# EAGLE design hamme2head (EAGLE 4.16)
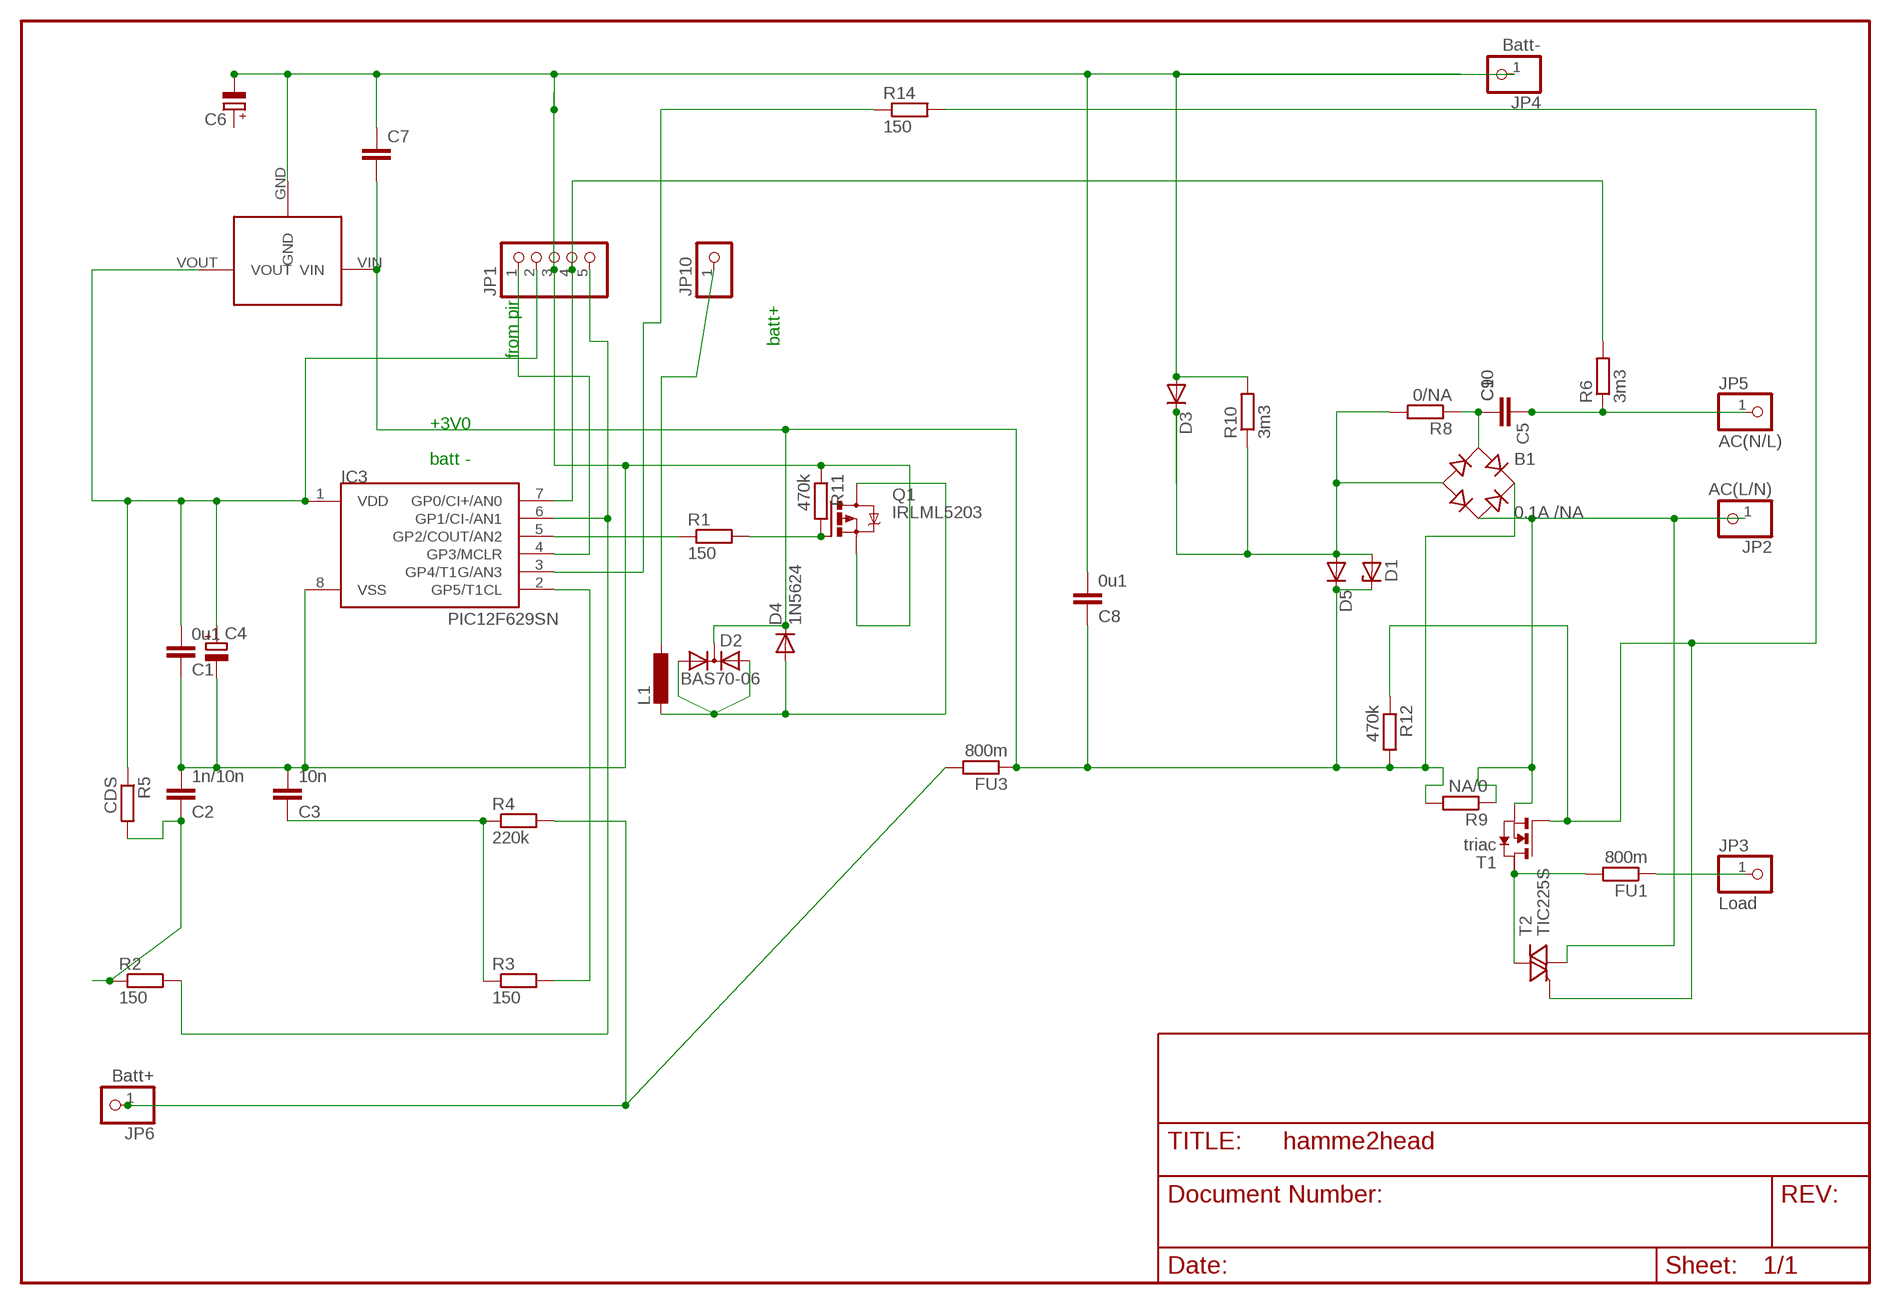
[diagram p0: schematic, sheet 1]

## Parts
B1  0.1A /NA  RECTIFIER-B40S  [B40S]
C1  0u1  C-EUC1206  [C1206]
C2  1n/10n  C-EUC1206  [C1206]
C3  10n  C-EUC1206  [C1206]
C4  CPOL-EUE2.5-6  [E2,5-6]
C5  C-EU050-025X075  [C050-025X075]
C6  CPOL-EUE2,5-6E  [E2,5-6E]
C7  C-EUC0805  [C0805]
C8  0u1  C-EUC1206  [C1206]
C9  C-EU075-032X103  [C075-032X103]
C10  C-EU102-043X133  [C102-043X133]
D1  ZENER-DIODESOT23  [SOT23]
D2  BAS70-06  [SOT23]
D3  DIODE-MELF-MLL41  [MELF-MLL41]
D4  1N5624  [DO201-15]
D5  DIODE-MINIMELF  [MINIMELF]
FU1  800m  R-EU_0204/5  [0204/5]
FU3  800m  R-EU_0204/7  [0204/7]
IC3  PIC12F629SN  [SO-08]
JP1  PINHD-1X5  [1X05]
JP2  AC(L/N)  PINHD-1X1  [1X01]
JP3  Load  PINHD-1X1  [1X01]
JP4  Batt-  PINHD-1X1  [1X01]
JP5  AC(N/L)  PINHD-1X1  [1X01]
JP6  Batt+  PINHD-1X1  [1X01]
JP10  PINHD-1X1  [1X01]
L1  L-EU2200-15.24  [2200-15.24]
Q1  IRLML5203  [MICRO3]
R1  150  R-EU_0207/15  [0207/15]
R2  150  R-EU_R0805  [R0805]
R3  150  R-EU_R0805  [R0805]
R4  220k  R-EU_R0805  [R0805]
R5  CDS  R-EU_0411/3V  [0411V]
R6  3m3  R-EU_R1206  [R1206]
R8  0/NA  R-EU_R0402  [R0402]
R9  NA/0  R-EU_R0402  [R0402]
R10  3m3  R-EU_R1206  [R1206]
R11  470k  R-EU_R0805  [R0805]
R12  470k  R-EU_R0805  [R0805]
R14  150  R-EU_0617/22  [0617/22]
T1  triac  NMOSSOT223  [SOT223]
T2  TIC225S  [TO220DS]
U$1  VREG-S  [TO92-S]

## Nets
GND: C1.1 C2.2 C3.2 C4.- C6.- C7.1 C8.2 D3.A IC3.8(VSS) JP1.3 JP4.1 Q1.2(S) R10.2 R11.1 U$1.GND
N$2: IC3.6(GP1/CI-/AN1) JP1.5 R2.2
N$4: R12.1 R14.2 T1.1(G) T2.G
N$5: D2.1(A1) D2.2(A2) D4.A L1.2 Q1.3(D)
N$7: C3.1 R3.1 R4.1
N$8: IC3.2(GP5/T1CL) R3.2
N$9: IC3.4(GP3/MCLR) JP1.1
N$11: C2.1 R2.1 R5.2
N$12: IC3.5(GP2/COUT/AN2) R1.1
N$14: IC3.7(GP0/CI+/AN0) JP1.4 R6.2
N$17: JP10.1 L1.1
N$18: FU1.1 JP3.1
N$19: FU1.2 T1.2(D) T2.A2
N$20: Q1.1(G) R1.2 R11.2
N$21: IC3.3(GP4/T1G/AN3) R14.1
N$23: B1.AC2 JP2.1 R9.1 T1.3(S) T2.A1
N$25: B1.- D1.1(A) D3.C D5.A R8.2 R10.1
N$26: B1.AC1 C5.2 C9.1 C10.1 R8.1
N$36: FU3.2 JP6.1 R4.2
N$37: C5.1 C9.2 C10.2 JP5.1 R6.1
RECT+: B1.+ C7.2 C8.1 D1.3(C) D2.3(C) D4.C D5.C FU3.1 R9.2 R12.2 U$1.VIN
VOUT+: C1.2 C4.+ IC3.1(VDD) JP1.2 R5.1 U$1.VOUT
Unconnected: C6.+ T1.4(D2)

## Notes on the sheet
- batt+
- from pir
- +3V0
- batt -

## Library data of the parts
B1 = rectifier:RECTIFIER-: Rectifier
C1-C3 C5 C8-C10 = rcl:C-EU: CAPACITOR, European symbol
C4 C6 = rcl(2):CPOL-EU: POLARIZED CAPACITOR, European symbol
C7 = rcl(2):C-EU: CAPACITOR, European symbol
D1 = diode-1:ZENER-DIODE: Z-Diode
D2 = diode-1:BAS70-06: Silicon Schottky Diodes General-purpose diode for high-speed switching
D3 D5 = diode-1:DIODE-: DIODE
D4 = diode:1N5624: DIODE
FU1 FU3 R1-R6 R8-R12 R14 = rcl:R-EU_: RESISTOR, European symbol
IC3 = microchip-3:PIC12F6*: uPC nW 1k Program Flash memory 2x Timer Comparator 10b A/D converter/ 4xIN
JP1 = pinhead(2):PINHD-1X5: PIN HEADER
JP2-JP6 = pinhead:PINHD-1X1: PIN HEADER
JP10 = pinhead(2):PINHD-1X1: PIN HEADER
L1 = rcl:L-EU: INDUCTOR, European symbol
Q1 = transistor-power:IRLML5203: HEXFET P-Channel Power MOSFET
T1 = zetex:NMOSSOT223: MOS FET
T2 = triac:TIC225S: TRIAC
U$1 = spoton:VREG-S: vreg aus spoton

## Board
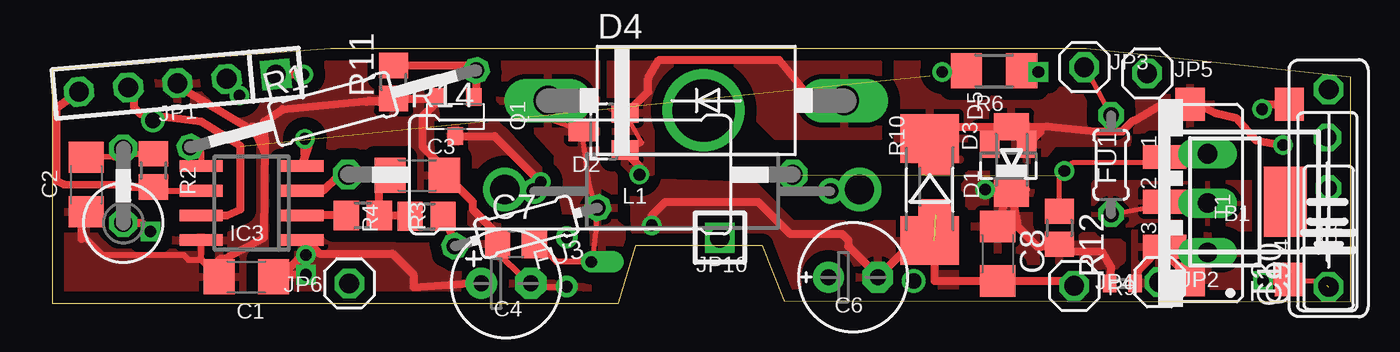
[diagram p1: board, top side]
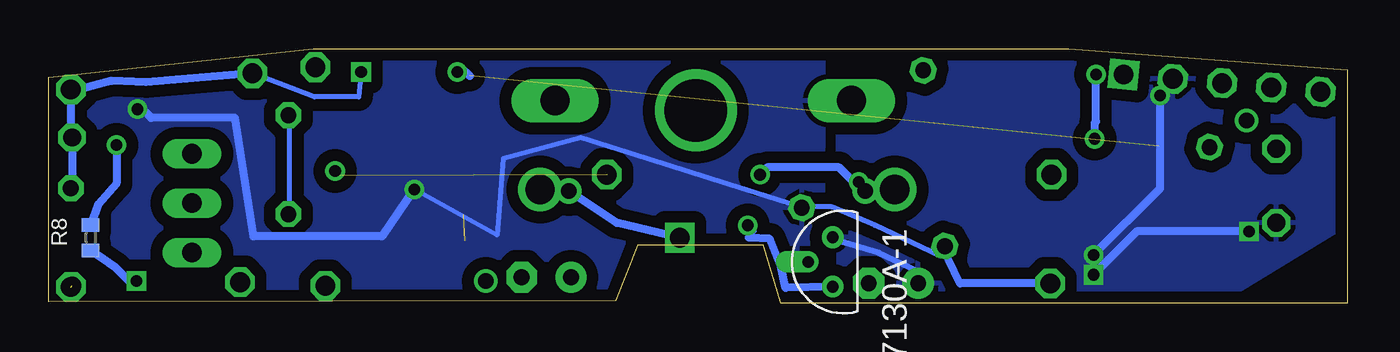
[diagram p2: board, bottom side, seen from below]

Size 66.76 x 13.08 mm. Coordinates in mm from the lower left corner, seen from the top.
Outline: 0,0 29.11,0 30,2.98 36.47,2.98 37.62,0.12 66.76,0.06 66.76,11.61 53.18,13.07 52.41,13.08 18,13.07 14.31,13.08 0,11.99 0,0
Copper layers (1*16): Top 0.035mm / dielectric 1.5mm / Bottom 0.035mm
Design rules "default": minimum track width 10mil, minimum drill 2mil, track to track 8mil, track to pad 8mil, pad to pad 8mil, via to via 8mil, smd to smd 8mil, copper to edge 1mil, drill to drill 8mil, minimum pad ring 10mil, minimum via ring 8mil, stop-mask expansion 4mil, vias tented up to drill 0mil, thermal gap 10mil

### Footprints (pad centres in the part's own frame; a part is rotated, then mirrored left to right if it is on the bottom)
B40S = smd 1.5 x 1.7: + -2.55,-4.5; - 2.55,-4.5; AC1 -2.55,4.5; AC2 2.55,4.5
C1206 = smd 1.6 x 1.8: 1 -1.4,0; 2 1.4,0
E2,5-6 = drill 0.813 pad 1.6 round: + -1.27,0 | drill 0.813 pad 1.6 octagon: - 1.27,0
C050-025X075 = drill 0.813 octagon: 1 -2.54,0; 2 2.54,0
E2,5-6E = drill 0.813 pad 1.575 round: + -1.27,0 | drill 0.813 pad 1.575 octagon: - 1.27,0
C0805 = smd 1.3 x 1.5: 1 -0.95,0; 2 0.95,0
C075-032X103 = drill 0.914 octagon: 1 -3.81,0; 2 3.81,0
C102-043X133 = drill 1.016 octagon: 1 -5.08,0; 2 5.08,0
SOT23 = smd 1 x 1.4: 1 -0.95,-1.1; 2 0.95,-1.1; 3 0,1.1
MELF-MLL41 = smd 2.5 x 3: A 2.625,0; C -2.625,0
DO201-15 = drill 1.499 long: A 7.62,0; C -7.62,0
MINIMELF = smd 1.4 x 1.8: A 1.7,0; C -1.7,0
0204/5 = drill 0.813 octagon: 1 -2.54,0; 2 2.54,0
0204/7 = drill 0.813 octagon: 1 -3.81,0; 2 3.81,0
SO-08 = smd 0.6 x 2.2: 1 -1.905,-2.6; 2 -0.635,-2.6; 3 0.635,-2.6; 4 1.905,-2.6; 5 1.905,2.6; 6 0.635,2.6; 7 -0.635,2.6; 8 -1.905,2.6
1X05 = drill 1.016 square: 1 -5.08,0 | drill 1.016 octagon: 2 -2.54,0; 3 0,0; 4 2.54,0; 5 5.08,0
1X01 = drill 1.016 octagon: 1 0,0
1X01' = drill 1.016 square: 1 0,0
2200-15.24 = drill 0.8 pad 1.27 round: 1 -7.62,0; 2 7.62,0
MICRO3 = smd 0.8 x 0.9: 1 -0.95,-1; 2 0.95,-1; 3 0,1
0207/15 = drill 0.813 octagon: 1 -7.62,0; 2 7.62,0
R0805 = smd 1.3 x 1.5: 1 -0.85,0; 2 0.85,0
0411V = drill 0.914 octagon: 1 -2.54,0; 2 1.27,0
R1206 = smd 1.6 x 1.803: 1 -1.422,0; 2 1.422,0
R0402 = smd 0.7 x 0.9: 1 -0.65,0; 2 0.65,0
0617/22 = drill 1.016 octagon: 1 -11.43,0; 2 11.43,0
SOT223 = smd 1.219 x 2.235: 1 -2.311,-3.099; 2 0,-3.099; 3 2.311,-3.099 | smd 3.6 x 2.2: 4 0,3.099
TO220DS = drill 1.016 long: A1 -2.54,-2.54; A2 0,-2.54; G 2.54,-2.54
TO92-S = drill 0.6 round: GND -2.54,0; VOUT 0,0 | drill 0.6 offset: VIN -1.27,1.27

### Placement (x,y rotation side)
B1  61.05,5.71 180 top
C1  9.98,1.34 0 top
C2  1.74,6.09 270 top
C3  18.76,6.56 0 top
C4  23.33,1.01 0 top
C5  65.62,3.36 270 top
C6  41.17,1.33 0 top
C7  23.84,3.04 0 top
C8  48.6,2.54 270 top
C9  65.56,4.69 90 top
C10  65.62,5.9 90 top
D1  49.15,7.06 180 top
D2  28.35,8.82 90 top
D3  45.11,5.84 270 top
D4  33.11,10.41 0 top
D5  49.32,7.36 90 top
FU1  54.43,7.11 270 top
FU3  24.36,3.91 195 top
IC3  10.25,5.14 90 top
JP1  6.43,11.3 185 top
JP2  56.92,1.07 0 top
JP3  53.05,12.12 0 top
JP4  52.54,0.88 0 top
JP5  56.29,11.81 0 top
JP6  15.27,1.01 0 top
JP10  [1X01']  34.32,3.36 0 top
L1  32.4,5.75 180 top
Q1  20.73,9.58 180 top
R1  14.44,9.99 15 top
R2  5.19,6.82 270 top
R3  15.96,4.5 180 top
R4  19.24,4.47 0 top
R5  3.65,6.66 90 top
R6  48.41,11.93 180 top
R8  64.6,3.36 90 bottom
R9  55.02,1.01 180 top
R10  45.43,5.96 270 top
R11  17.55,11.36 90 top
R12  51.78,3.87 270 top
R14  26.63,6.6 0 top
T1  60.29,5.2 270 top
T2  56.86,5.14 90 top
U$1  26.45,3.38 90 bottom

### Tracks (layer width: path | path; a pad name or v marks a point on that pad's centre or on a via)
GND  (via drill 0.6)  (1 unrouted)
  Top 0.305: C1.1 8.55,1.34 8.53,1.33 8.12,1.74 7.68,2.19 | IC3.8 7.65,2.21 7.68,2.19 | C7.1 22.63,2.85 24.47,1.01 C4.- 24.77,0.84 U$1.GND | 7.68,2.19 7.71,2.22 7.01,2.22 6.76,2.47 2.57,2.47 1.74,3.3 1.49,3.3 | 7.68,2.19 | C2.2 1.48,4.75 1.3,4.57
  Top 0.406: 10.95,8.31 10.88,3.36 8.85,2.28 8.66,2.28 8.12,1.74 | 8.12,1.74 8.09,1.71 | 8.12,1.74 | C7.1 22.89,3.17 22.95,3.23 22.82,3.36 22.82,3.61 21.62,4.82 21.62,5.2 20.6,6.22 20.54,6.22 20.16,6.6 | JP4.1 52.41,0.88 52.41,1.14 C8.2 45.36,1.14 45.36,3.21 D3.A 44.33,3.21 C6.- 42.44,1.39 40.92,2.92 40.92,3.23 40.6,3.55 37.94,3.55 36.28,5.2 31.52,5.2 30.82,4.5 v30.82,4 | 20.16,6.6 | 20.16,6.6 C3.2 20.16,6.91 19.01,8.06 19.01,9.58 19.78,10.35 Q1.2 19.78,10.54 19.65,10.41 19.54,10.51 R11.1 17.55,10.41 17.49,10.35 16.79,10.35 | 16.79,10.35 16.15,10.35 | C2.2 1.86,4.69 1.49,4.31 1.49,3.3 | JP1.3 6.43,11.24 6.7,10.97 6.75,10.97 10.12,8.95 10.31,9.08 10.88,7.81 10.95,8.31 | 10.95,8.31 10.88,9.33 11.84,9.96 16.28,10.41 16.79,10.41 16.79,10.35
  Bottom 0.406: U$1.GND 28.88,0.78 29.11,1.9 29.68,3.3 30.76,3.36 30.57,3.74 v30.82,4
  pour Top (isolate 0.61, rank 3): 29.87,5.39 29.93,3.74 30,3.55 36.03,3.55 36.98,2.6 36.98,1.84 38.32,0.5 46.32,0.5 46.44,0.63 46.44,1.65 44.03,4.06 38.06,4.06 36.09,6.03 30.44,6.22 30.06,5.84 30,5.65
  pour Top (isolate 0.61, rank 3): 0.15,11.49 0.15,1.27 0.85,0.57 27.71,0.57 25.3,3.93 20.85,4.69 19.08,12.69 1.74,12.57 0.66,11.49
N$2
  Top 0.305: R2.2 5.19,5.88 5.3,5.77 IC3.6
  Top 0.406: R2.2 3.51,5.97 3.39,6.09 0.59,6.1 0.22,6.28 0.22,10.03 JP1.5 | JP1.5 1.49,10.98 | JP1.5
N$3
  Bottom 0.254: 20.92,2.41 24.28,4 26.51,4.95 27.97,4.95
N$4  (1 unrouted)
  Top 0.254: R12.1 51.78,6.54 52.48,7.23 56.29,7.23 56.48,7.42 56.98,7.42 | T2.G 59.33,7.74 59.02,7.42 56.98,7.42 | 56.98,7.42 56.98,7.55 57.02,7.51 T1.1
N$5  (via drill 0.6)
  Top 0.254: D2.1 30.32,8.25 D2.2 | L1.2 24.85,6.03
  Top 0.406: Q1.3 22.74,8.58 v25.11,6.22 25.11,6.03 24.83,5.75 L1.2 | D4.A 39.08,10.41 37.36,12.5 31.2,12.5 30.63,11.55 30.63,10.85 29.55,9.77 D2.2 | D2.1 29.45,7.83 29.43,7.81 30.19,7.04 v30.19,6.6
  Bottom 0.406: v25.11,6.22 25.36,6.22 26.12,6.98 29.81,6.98 v30.19,6.6
  pour Top (isolate 0.61, rank 3): 28.73,10.03 28.73,12.69 28.79,12.76 42,12.76 42.7,12.06 42.7,8.76 42.51,8.57 37.24,8.57 35.46,10.35 31.78,10.35 30.76,9.33 30.76,6.79 30.82,6.73 29.87,6.73 28.98,7.62 28.98,9.9 28.85,10.03
  pour Top (isolate 0.61, rank 2): 20.41,9.01 22.95,9.14 25.49,6.34 23.96,4.82 23.2,4.82 20.73,7.3
N$7
  Top 0.406: C3.1 17.36,6.48 17.36,6.47 16.81,5.92 R3.1 18.25,4.5 18.31,4.44 18.34,4.47 R4.1
N$8
  Top 0.406: R3.2 15.08,4.5 15.01,4.44 14.95,4.5 IC3.2
N$9  (via drill 0.6)
  Top 0.406: IC3.4 12.85,7.1 13.17,8.06 13.17,8.19 12.98,7.62 v12.98,8.44 | JP1.1 v12.91,11.75 v12.92,11.74
  Bottom 0.406: v12.98,8.44 12.98,9.27 12.92,9.33 v12.92,11.74
N$11
  Top 0.305: 3.91,7.67 4.03,7.67 R2.1 | C2.1 3.14,7.55
  Top 0.406: 3.14,7.55 3.39,7.55 3.64,7.81 R5.2 3.71,7.93 4.03,7.62 4.03,7.67
N$12
  Top 0.305: R1.1 7.49,8.22 7.58,8.25 7.65,7.68 IC3.5
N$14  (via drill 0.6)  (1 unrouted)
  Top 0.406: IC3.7 8.98,4.5 9.68,4.82 9.68,8.06 7.65,9.33 4.53,9.71 4.22,10.03 4.22,10.92 4.05,11.08 JP1.4 | R6.2 45.81,11.93 v45.75,11.87
  Bottom 0.406: v45.75,11.87 45.3,11.87 45.11,11.68
N$15  (via drill 1.5)
  other vias: 41.49,5.84
N$16  (via drill 1.5)
  other vias: 23.27,5.84
N$17
  Bottom 0.406: L1.1 37.55,4.12 JP10.1
N$18
  Top 0.254: JP3.1 53.11,12.12 FU1.1
N$19
  Top 0.254: 57.23,5.08 57.19,5.13 T1.2 59.27,5.2 59.4,5.08 T2.A2 | FU1.2 57.23,5.08 | 57.23,5.08 57.24,5.08
  pour Top (isolate 0.61): 53.62,6.22 62.26,6.22 62.51,5.96 62.51,3.87 62.57,3.81 60.92,3.81 60.73,4 53.68,4 53.56,4.19 53.56,6.15
N$20
  Top 0.406: R11.2 21.85,12.21 21.93,12.12 21.8,11.99 R1.2 21.8,10.8 21.81,10.79 21.68,10.66 Q1.1
N$21
  Top 0.406: IC3.3 13.93,5.77 14.63,6.47 15.08,6.47 R14.1
N$23
  Top 0.406: T2.A1 59.4,2.47 58.5,1.57 B1.AC2 58.5,1.28 57.19,2.59 T1.3 57,2.87 55.86,1.73 R9.1
  pour Top (isolate 0.61): 55.65,0.44 60.99,0.5 60.99,3.36 55.65,3.61
N$24  (via drill 0.6)
  other vias: 52.03,6.79
N$25  (via drill 0.6)
  Top 0.406: 50.81,9.06 51.14,9.08 53.62,8.82 55.02,8.82 55.59,9.39 55.65,9.39 57.04,10.21 B1.- 58.75,10.21 58.83,10.28 59.78,9.77 60.86,9.52 61.87,8.38 v63.27,8.12 | 50.81,9.06 D5.A 46.24,9.06 45.62,8.44 45.6,8.46 D3.C 45.43,7.3 | D1.1 50.16,8.16 50.81,8.8 50.81,9.06
  Bottom 0.406: R8.2 64.21,5.09 63.27,6.16 v63.27,8.12
  pour Top (isolate 0.61): 59.14,11.04 56.03,11.04 55.14,10.15 55.14,9.9 54.64,9.39 54.45,9.39 53.3,10.54 47.02,12.57 43.46,12.57 43.46,7.04 49.87,7.36 50.83,7.36 51.52,8.25 55.33,8.25 56.29,9.08 59.14,9.08 59.21,9.14 59.65,10.41 59.27,10.92
N$26  (via drill 0.6)  (1 unrouted)
  Top 0.254: C10.1 65.68,0.88 65.43,1.14 63.65,1.14
  Top 0.406: B1.AC1 63.6,1.19 63.65,1.14 v62.26,1.14
  Bottom 0.406: R8.1 63.33,1.84 62.64,1.14 v62.26,1.14
N$27
  Bottom 0.254: 54.38,4.63 54.38,9.46
N$28  (via drill 3.2)
  other vias: 33.49,9.9
N$31  (via drill 0.8)
  other vias: 44.29,1.14
N$32  (via drill 0.8)
  other vias: 5.17,9.39
N$36
  Top 0.406: FU3.2 20.85,2.85 R4.2
  Bottom 0.406: JP6.1 19.9,1.01 20.79,2.85 FU3.2
N$37  (via drill 0.6)
  Top 0.254: R6.1 50.06,11.87 v50.7,11.87
  Bottom 0.254: JP5.1 53.11,10.6 50.83,10.6 v50.7,11.87
  Bottom 0.406: JP5.1 61.75,11.36 63.53,11.42 65.43,10.92 65.49,10.98 C10.2 65.62,8.38 65.56,8.44 C9.2 65.56,5.9 65.62,5.84 C5.1
RECT+  (via drill 0.6)
  Top 0.254: D4.C 25.55,10.22 25.55,9.46 D2.3 27.58,6.16 27.97,4.82 FU3.1 27.97,3.68 27.78,2.09 U$1.VIN
  Top 0.305: C7.2 24.54,3.49 25.91,2.11 U$1.VIN
  Top 0.406: 49.23,5.71 48.98,5.9 | 49.31,5.96 D1.3 49.34,5.73 | C8.1 48.6,4.31 49.23,5.71 | 49.74,5.66 49.56,5.65 | 49.74,5.66 D5.C 49.64,3.91 50.67,2.88 R12.2 51.78,3.04 | 49.31,5.96 49.23,5.71 | 49.31,5.96 49.74,5.66 | B1.+ 62.44,10.21 v62.19,9.96 | 49.34,5.73 49.3,5.65 | v47.97,5.84 50.06,5.84 49.34,5.73 | R9.2 54.43,1.85 53.94,2.66 52.16,2.66 51.78,3.04 | 51.78,3.04 51.71,3.11
  Bottom 0.254: v47.97,5.84 43.71,3.49 43.4,7.42 39.4,8.5 27.9,4.88 FU3.1
  Bottom 0.406: v62.19,9.96 61.94,9.96 61.49,9.52 57.18,9.52 56.22,3.42 49.62,3.42 v47.97,5.84
  pour Bottom (isolate 0.61): 63.72,11.17 57.18,12.25 55.31,12.42 53.62,12.76 26.95,12.76 26.95,9.2 27.01,4.25 27.33,2.79 38.06,0.57 64.99,0.44 65.05,10.85
  pour Top (isolate 0.61): 46.51,6.66 46.51,2.15 52.73,2.15 53.18,0.44 55.02,0.44 55.02,2.98 54.57,3.42 50.95,3.42 50.32,4.06 50.32,6.15 49.87,6.6 46.76,6.6
  pour Top (isolate 0.61, rank 3): 23.01,12.76 27.97,12.76 27.97,7.42 28.85,6.54 28.85,4.19 29.24,3.87 29.43,2.22 28.98,1.77 28.09,1.77 27.27,2.6 27.27,3.68 26.44,4.5 25.93,7.3 24.92,8.31 24.66,8.63 24.35,8.95 23.01,10.47
VOUT+  (via drill 0.6)
  Top 0.305: C4.+ 22.12,0.95
  Top 0.406: 11.57,1.34 11.58,1.33 11.71,1.33 | IC3.1 12.79,3.23 13.11,2.92 | 22.25,1.01 C4.+ 21.49,1.01 18.57,0.82 18.57,1.46 17.49,2.54 13.74,2.54 13.04,3.23 IC3.1 | 11.71,1.33 13.11,2.73 13.11,3.04 12.92,3.23 IC3.1 | 11.57,1.34 11.65,1.27 11.71,1.33 | 11.57,1.34 C1.2 11.6,1.34 11.77,1.52 11.84,1.46 v13.04,1.46 13.04,1.52 12.98,1.58 13.04,1.65 v13.04,2.47 | R5.1 4.6,4.12 v5.04,3.68 | JP1.2 8.96,11.31 v9.61,10.66
  Bottom 0.305: C4.+ 22.06,1.65 24.09,2.6 26.25,3.23 26.4,3.38 U$1.VOUT
  Bottom 0.406: v5.04,3.68 10.82,3.68 v13.04,1.46 | v9.61,10.66 9.61,5.9 v13.04,2.47
  pour Bottom (isolate 0.61): 0.28,11.17 0.28,3.87 5.93,0.44 13.74,0.5 26.12,0.5 26.19,12.63 10.57,12.63 0.79,11.62
  pour Top (isolate 0.61, rank 2): 12.15,3.3 12.15,0.12 22.5,0.38 22.63,0.25 22.63,1.07 21.87,1.84 19.71,1.84 19.52,2.03 19.52,2.79 19.27,3.04 19.01,3.04 18.82,3.23 14.5,3.23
